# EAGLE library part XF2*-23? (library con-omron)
OMRON FPC Connector Source : http://www.omron.com/ecb/products/pdf/fpc.pdf
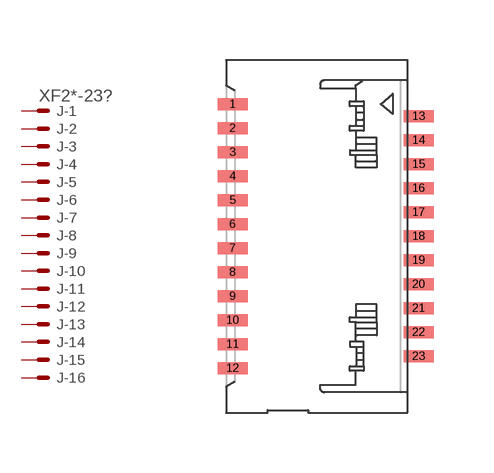
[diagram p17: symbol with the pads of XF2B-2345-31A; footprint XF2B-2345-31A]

Designator prefix J; gates -1=PV -2=P -3=P -4=P -5=P -6=P -7=P -8=P -9=P -10=P -11=P -12=P -13=P -14=P -15=P -16=P -17=P -18=P -19=P -20=P -21=P -22=P -23=P

## XF2B-2345-31A (MPN: XF2B-2345-31A; OC_FARNELL: unknown; OC_NEWARK: 37M0751)  [XF2B-2345-31A]
1  -1:MSV  pas
2  -2:MS  pas
3  -3:MS  pas
4  -4:MS  pas
5  -5:MS  pas
6  -6:MS  pas
7  -7:MS  pas
8  -8:MS  pas
9  -9:MS  pas
10  -10:MS  pas
11  -11:MS  pas
12  -12:MS  pas
13  -13:MS  pas
14  -14:MS  pas
15  -15:MS  pas
16  -16:MS  pas
17  -17:MS  pas
18  -18:MS  pas
19  -19:MS  pas
20  -20:MS  pas
21  -21:MS  pas
22  -22:MS  pas
23  -23:MS  pas

## Footprint XF2B-2345-31A (pad centres in mm)
Rotary Backlock Type (0.3 mm-pitch) Source : http://www.omron.com/ecb/products/pdf/fpc.pdf
smd 0.75 x 0.3: 1 -2.325,3.3; 2 -2.325,2.7; 3 -2.325,2.1; 4 -2.325,1.5; 5 -2.325,0.9; 6 -2.325,0.3; 7 -2.325,-0.3; 8 -2.325,-0.9; 9 -2.325,-1.5; 10 -2.325,-2.1; 11 -2.325,-2.7; 12 -2.325,-3.3; 13 2.325,3; 14 2.325,2.4; 15 2.325,1.8; 16 2.325,1.2; 17 2.325,0.6; 18 2.325,0; 19 2.325,-0.6; 20 2.325,-1.2; 21 2.325,-1.8; 22 2.325,-2.4; 23 2.325,-3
